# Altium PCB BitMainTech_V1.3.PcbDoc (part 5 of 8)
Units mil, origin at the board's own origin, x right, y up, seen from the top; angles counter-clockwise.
Board outline 9842.52 x 6082.68 mil, 4 copper layers (Top Layer, Mid-Layer 1, Mid-Layer 2, Bottom Layer); 987 components, 282 nets, 3694 pads, 3174 vias.
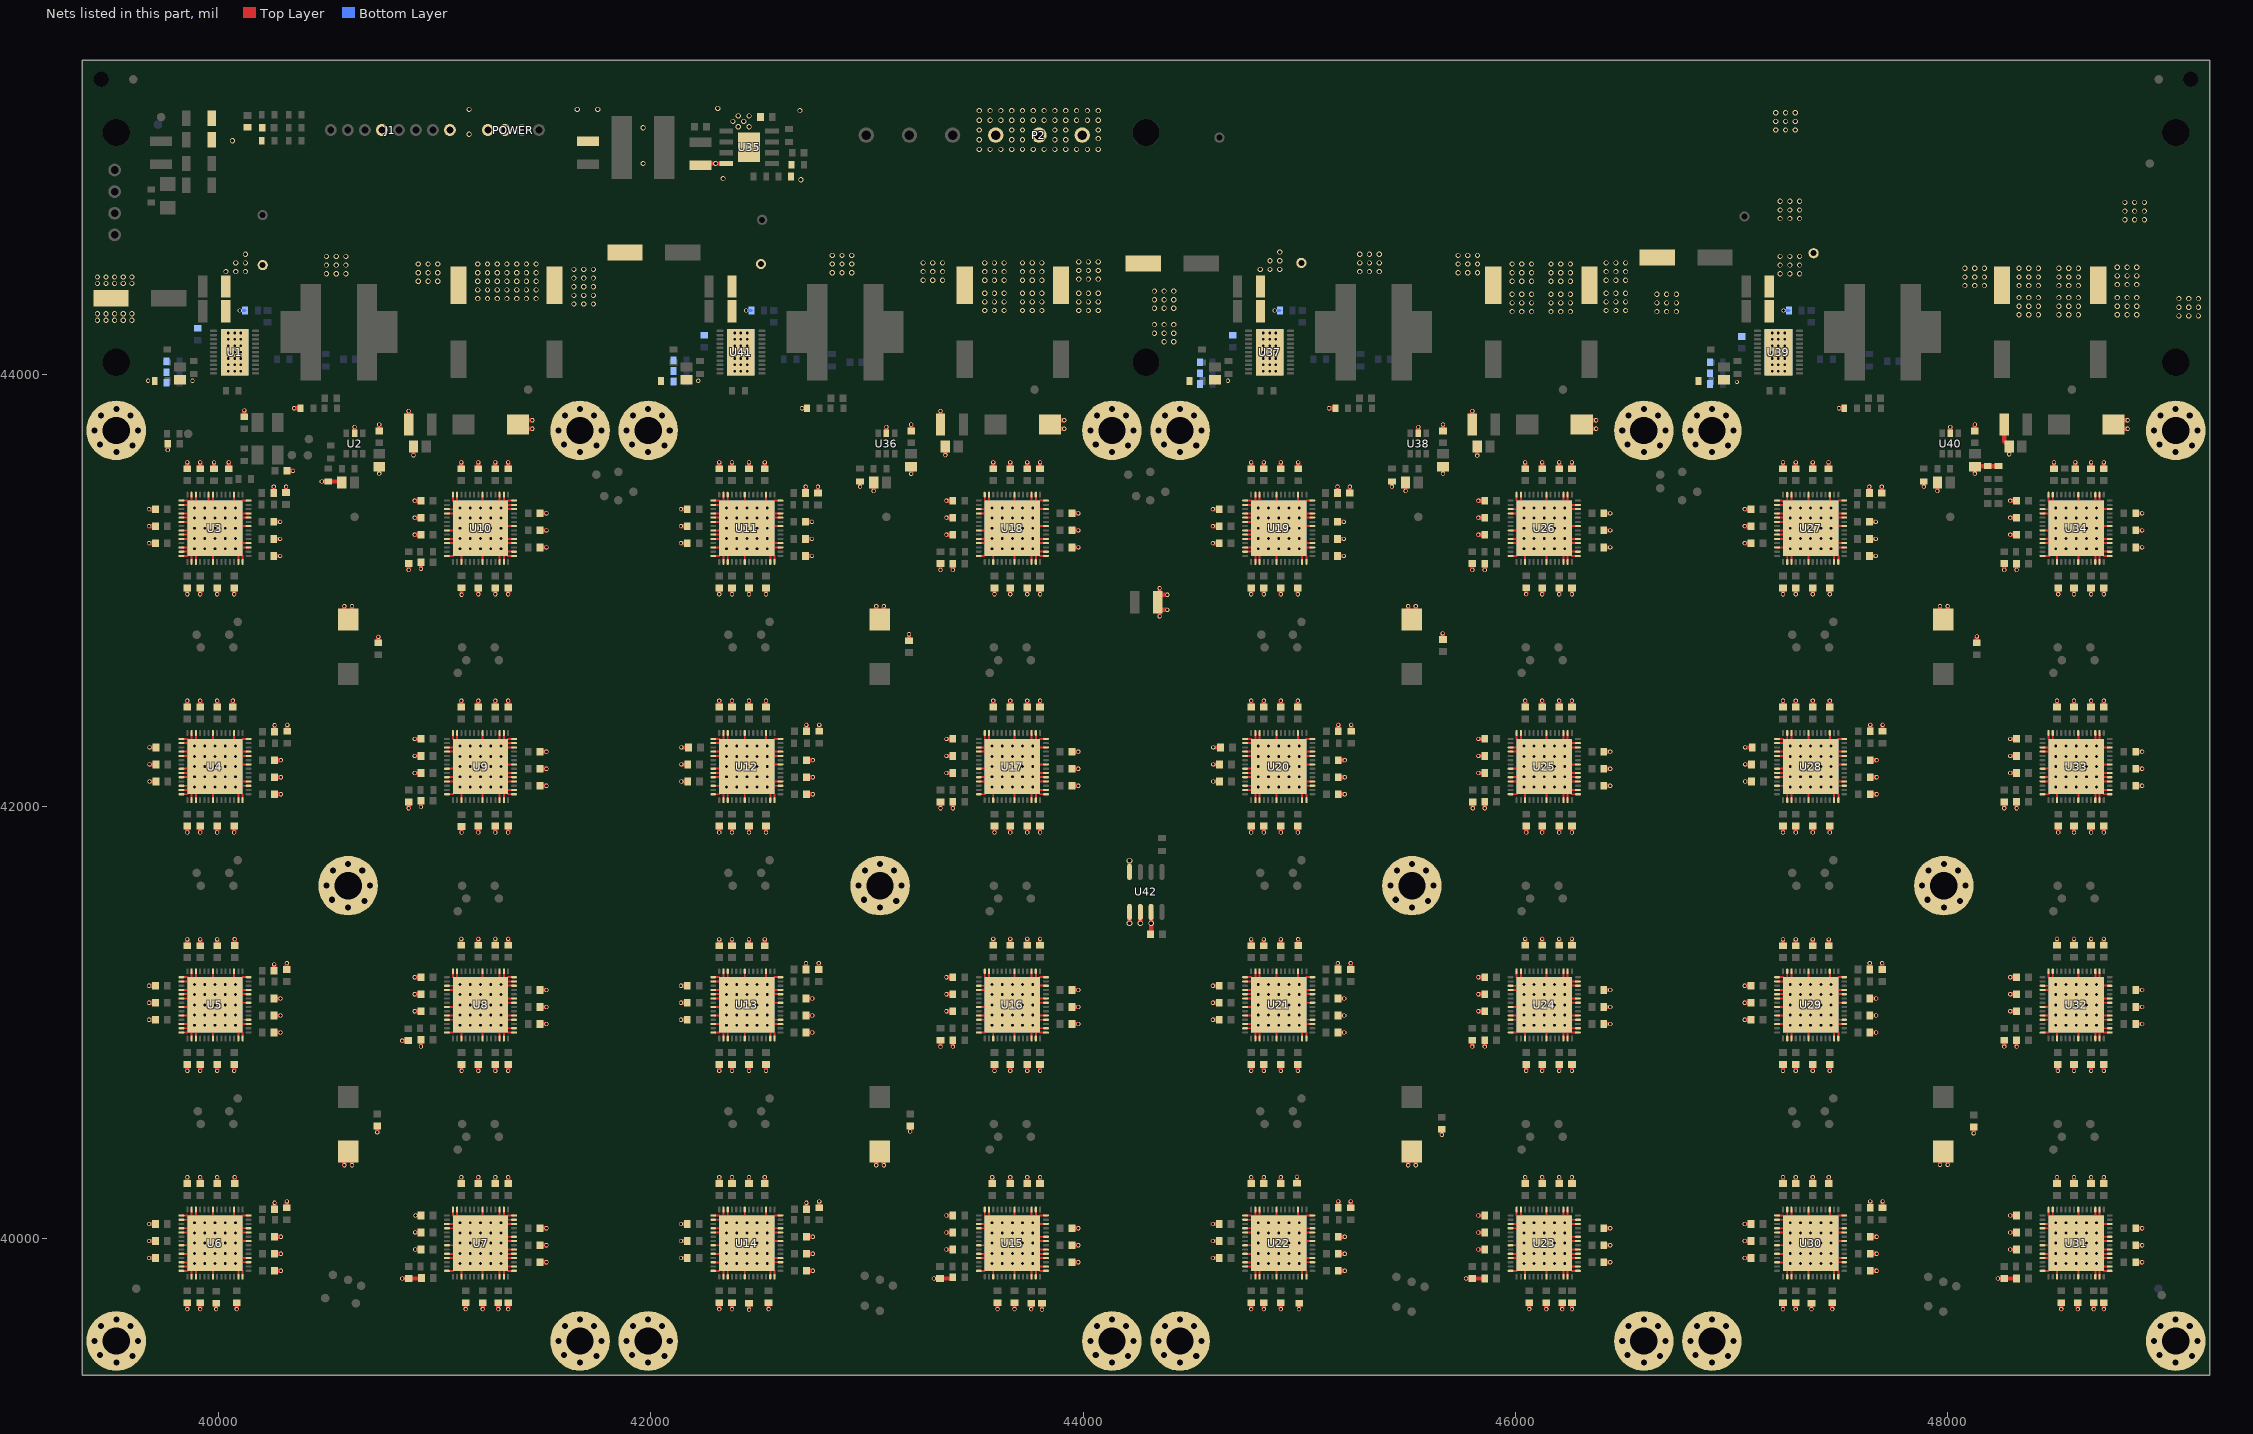
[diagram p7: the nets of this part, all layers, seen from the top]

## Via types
v1: diameter 19, hole 12, Top Layer to Bottom Layer, 1347 vias
v2: diameter 25.98, hole 12.99, Top Layer to Bottom Layer, 800 vias
v3: diameter 24, hole 16, Top Layer to Bottom Layer, 778 vias
v4: diameter 50, hole 28, Top Layer to Bottom Layer, 160 vias
v5: diameter 19.68, hole 11.81, Top Layer to Bottom Layer, 84 vias
v6: diameter 26, hole 18, Top Layer to Bottom Layer, 5 vias

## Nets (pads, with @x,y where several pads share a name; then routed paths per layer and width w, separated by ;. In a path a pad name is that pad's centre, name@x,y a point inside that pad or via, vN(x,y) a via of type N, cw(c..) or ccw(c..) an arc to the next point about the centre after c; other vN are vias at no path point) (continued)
GND: (continued)
  Top Layer w9: U6.28@39828.74,39852.36 39856.3,39852.36 U6.57@39862.2,39858.27 ; U6.27@39828.74,39872.05 U6.57@39872.05,39872.05 ; U6.26@39828.74,39891.73 U6.57@39872.05,39891.73 ; U6.24@39828.74,39931.1 U6.57@39872.05,39931.1 ; U6.22@39828.74,39970.47 U6.57@39872.05,39970.47 ; U6.19@39828.74,40029.53 U6.57@39872.05,40029.53 ; U6.18@39828.74,40049.21 U6.57@39872.05,40049.21 ; U6.16@39828.74,40088.58 U6.57@39872.05,40088.58 ; U6.15@39828.74,40108.27 39856.3,40108.27 U6.57@39862.2,40102.36 ; U5.28@39828.74,40954.72 39856.3,40954.72 U5.57@39862.2,40960.63 ; U5.27@39828.74,40974.41 U5.57@39872.05,40974.41 ; U5.26@39828.74,40994.09 U5.57@39872.05,40994.09 ; U5.24@39828.74,41033.46 U5.57@39872.05,41033.46 ; U5.22@39828.74,41072.83 U5.57@39872.05,41072.83 ; U5.20@39828.74,41112.2 U5.57@39872.05,41112.2 ; U5.19@39828.74,41131.89 U5.57@39872.05,41131.89 ; U5.18@39828.74,41151.57 U5.57@39872.05,41151.57 ; U5.16@39828.74,41190.94 U5.57@39872.05,41190.94 ; U5.15@39828.74,41210.63 39856.3,41210.63 U5.57@39862.2,41204.72 ; U4.28@39828.74,42057.09 39856.3,42057.09 U4.57@39862.2,42062.99 ; U4.27@39828.74,42076.77 U4.57@39872.05,42076.77 ; U4.26@39828.74,42096.46 U4.57@39872.05,42096.46 ; U4.24@39828.74,42135.83 U4.57@39872.05,42135.83 ; U4.23@39828.74,42155.51 U4.57@39872.05,42155.51 ; U4.22@39828.74,42175.2 U4.57@39872.05,42175.2 ; U4.19@39828.74,42234.25 U4.57@39872.05,42234.25 ; U4.18@39828.74,42253.94 U4.57@39872.05,42253.94 ; U4.16@39828.74,42293.31 U4.57@39872.05,42293.31 ; U4.15@39828.74,42312.99 39856.3,42312.99 U4.57@39862.2,42307.09 ; U3.28@39828.74,43159.45 39856.3,43159.45 U3.57@39875.98,43179.13 ; U3.27@39828.74,43179.13 U3.57@39875.98,43179.13 ; U3.26@39828.74,43198.82 U3.57@39895.67,43198.82 ; U3.24@39828.74,43238.19 U3.57@39935.04,43238.19 ; U3.23@39828.74,43257.87 U3.57@39935.04,43257.87 ; U3.22@39828.74,43277.56 U3.57@39974.41,43277.56 ; U3.20@39828.74,43316.93 U3.57@39935.04,43316.93 ; U3.19@39828.74,43336.61 U3.57@39935.04,43336.61 ; U3.18@39828.74,43356.3 U3.57@39915.35,43356.3 ; U3.16@39828.74,43395.67 U3.57@39875.98,43395.67 ; U3.15@39828.74,43415.35 39856.3,43415.35 U3.57@39875.98,43395.67 ; U6.30@39875.98,39824.8 U6.57@39875.98,39868.11 ; U6.57@39875.98,40092.52 U6.13@39875.98,40135.83 ; U5.30@39875.98,40927.17 U5.57@39875.98,40970.47 ; U5.57@39875.98,41194.88 U5.13@39875.98,41238.19 ; U4.30@39875.98,42029.53 U4.57@39875.98,42072.83 ; U4.57@39875.98,42297.24 U4.13@39875.98,42340.55 ; U3.30@39875.98,43131.89 U3.57@39875.98,43179.13 ; U3.13@39875.98,43442.91 U3.57@39875.98,43395.67 ; U6.31@39895.67,39824.8 U6.57@39895.67,39868.11 ; U6.57@39895.67,40092.52 U6.12@39895.67,40135.83 ; U5.31@39895.67,40927.17 U5.57@39895.67,40970.47 ; U5.57@39895.67,41194.88 U5.12@39895.67,41238.19 ; U4.31@39895.67,42029.53 U4.57@39895.67,42072.83 ; U4.57@39895.67,42297.24 U4.12@39895.67,42340.55 ; U3.31@39895.67,43131.89 U3.57@39895.67,43198.82 ; U3.12@39895.67,43442.91 U3.57@39895.67,43375.98 ; U3.9@39954.72,43442.91 U3.57@39954.72,43316.93 ; U6.35@39974.41,39824.8 U6.57@39974.41,39868.11 ; U6.57@39974.41,40092.52 U6.8@39974.41,40135.83 ; U5.35@39974.41,40927.17 U5.57@39974.41,40970.47 ; U5.57@39974.41,41194.88 U5.8@39974.41,41238.19 ; U4.35@39974.41,42029.53 U4.57@39974.41,42072.83 ; U4.57@39974.41,42297.24 U4.8@39974.41,42340.55 ; U3.35@39974.41,43131.89 U3.57@39974.41,43277.56 ; U3.8@39974.41,43442.91 U3.57@39974.41,43297.24 ; U6.57@40072.83,40092.52 U6.3@40072.83,40135.83 ; U5.57@40072.83,41194.88 U5.3@40072.83,41238.19 ; U4.57@40072.83,42297.24 U4.3@40072.83,42340.55 ; U3.3@40072.83,43442.91 U3.57@40072.83,43375.98 ; U6.41@40092.52,39824.8 U6.57@40092.52,39868.11 ; U5.41@40092.52,40927.17 U5.57@40092.52,40970.47 ; U4.41@40092.52,42029.53 U4.57@40092.52,42072.83 ; U3.41@40092.52,43131.89 U3.57@40092.52,43179.13 ; U6.57@40096.46,39911.42 U6.46@40139.76,39911.42 ; U6.57@40096.46,39990.16 U6.50@40139.76,39990.16 ; U6.57@40096.46,40029.53 U6.52@40139.76,40029.53 ; U6.57@40096.46,40049.21 U6.53@40139.76,40049.21 ; U5.57@40096.46,41013.78 U5.46@40139.76,41013.78 ; U5.57@40096.46,41092.52 U5.50@40139.76,41092.52 ; U5.57@40096.46,41131.89 U5.52@40139.76,41131.89 ; U5.57@40096.46,41151.57 U5.53@40139.76,41151.57 ; U4.57@40096.46,42116.14 U4.46@40139.76,42116.14 ; U4.57@40096.46,42194.88 U4.50@40139.76,42194.88 ; U4.57@40096.46,42234.25 U4.52@40139.76,42234.25 ; U4.57@40096.46,42253.94 U4.53@40139.76,42253.94 ; U6.57@40098.43,40094.49 40112.2,40108.27 U6.56@40139.76,40108.27 ; U5.57@40098.43,41196.85 40112.2,41210.63 U5.56@40139.76,41210.63 ; U4.57@40098.43,42299.21 40112.2,42312.99 U4.56@40139.76,42312.99 ; U6.57@40102.36,39862.2 40112.2,39852.36 U6.42@40112.2,39824.8 ; U5.57@40102.36,40964.57 40112.2,40954.72 U5.42@40112.2,40927.17 ; U4.57@40102.36,42066.93 40112.2,42057.09 U4.42@40112.2,42029.53 ; U3.42@40112.2,43131.89 40112.2,43159.45 U3.57@40092.52,43179.13 ; U3.46@40139.76,43218.5 U3.57@40053.15,43218.5 ; U3.50@40139.76,43297.24 U3.57@39994.09,43297.24 ; U3.52@40139.76,43336.61 U3.57@40033.46,43336.61 ; U3.53@40139.76,43356.3 U3.57@40053.15,43356.3 ; U3.56@40139.76,43415.35 40112.2,43415.35 v2(40078.74,43381.89) U3.57@40072.83,43375.98 ; U7.56@41057.09,39852.36 41084.65,39852.36 U7.57@41098.43,39866.14 ; U7.53@41057.09,39911.42 U7.57@41100.39,39911.42 ; U7.52@41057.09,39931.1 U7.57@41100.39,39931.1 ; U7.50@41057.09,39970.47 U7.57@41100.39,39970.47 ; U7.46@41057.09,40049.21 U7.57@41100.39,40049.21 ; U8.56@41057.09,40954.72 41084.65,40954.72 U8.57@41098.43,40968.5 ; U8.53@41057.09,41013.78 U8.57@41100.39,41013.78 ; U8.52@41057.09,41033.46 U8.57@41100.39,41033.46 ; U8.50@41057.09,41072.83 U8.57@41100.39,41072.83 ; U8.46@41057.09,41151.57 U8.57@41100.39,41151.57 ; U9.56@41057.09,42057.09 41084.65,42057.09 U9.57@41098.43,42070.87 ; U9.53@41057.09,42116.14 U9.57@41100.39,42116.14 ; U9.52@41057.09,42135.83 U9.57@41100.39,42135.83 ; U9.50@41057.09,42175.2 U9.57@41100.39,42175.2 ; U9.46@41057.09,42253.94 U9.57@41100.39,42253.94 ; U10.56@41057.09,43159.45 41084.65,43159.45 v2(41118.11,43192.91) U10.57@41124.02,43198.82 ; U10.53@41057.09,43218.5 U10.57@41143.7,43218.5 ; U10.52@41057.09,43238.19 U10.57@41163.39,43238.19 ; U10.50@41057.09,43277.56 41202.76,43277.56 v2(41165.35,43240.16) U10.57@41163.39,43238.19 ; U10.46@41057.09,43356.3 U10.57@41143.7,43356.3 ; U7.42@41084.65,40135.83 41084.65,40108.27 U7.57@41090.55,40102.36 ; U8.42@41084.65,41238.19 41084.65,41210.63 U8.57@41090.55,41204.72 ; U9.42@41084.65,42340.55 41084.65,42312.99 U9.57@41090.55,42307.09 ; U10.42@41084.65,43442.91 41084.65,43415.35 41104.33,43395.67 U10.41@41104.33,43442.91 ; U7.57@41104.33,40092.52 U7.41@41104.33,40135.83 ; U8.57@41104.33,41194.88 U8.41@41104.33,41238.19 ; U9.57@41104.33,42297.24 U9.41@41104.33,42340.55 ; U7.3@41124.02,39824.8 U7.57@41124.02,39868.11 ; U8.3@41124.02,40927.17 U8.57@41124.02,40970.47 ; U9.3@41124.02,42029.53 U9.57@41124.02,42072.83 ; U10.3@41124.02,43131.89 U10.57@41124.02,43198.82 ; U7.8@41222.44,39824.8 U7.57@41222.44,39868.11 ; U7.57@41222.44,40092.52 U7.35@41222.44,40135.83 ; U8.8@41222.44,40927.17 U8.57@41222.44,40970.47 ; U8.57@41222.44,41194.88 U8.35@41222.44,41238.19 ; U9.8@41222.44,42029.53 U9.57@41222.44,42072.83 ; U9.57@41222.44,42297.24 U9.35@41222.44,42340.55 ; U10.8@41222.44,43131.89 41222.44,43277.56 v2(41259.84,43240.16) U10.57@41261.81,43238.19 ; U10.35@41222.44,43442.91 41222.44,43297.24 U10.22@41368.11,43297.24 ; U7.12@41301.18,39824.8 U7.57@41301.18,39868.11 ; U7.57@41301.18,40068.9 U7.26@41368.11,40068.9 ; U7.57@41301.18,40092.52 U7.31@41301.18,40135.83 ; U8.12@41301.18,40927.17 U8.57@41301.18,40970.47 ; U8.57@41301.18,41171.26 U8.26@41368.11,41171.26 ; U8.57@41301.18,41194.88 U8.31@41301.18,41238.19 ; U9.12@41301.18,42029.53 U9.57@41301.18,42072.83 ; U9.57@41301.18,42297.24 U9.31@41301.18,42340.55 ; U10.12@41301.18,43131.89 U10.57@41301.18,43198.82 ; U10.31@41301.18,43442.91 41301.18,43375.98 U10.26@41368.11,43375.98 ; U7.13@41320.87,39824.8 U7.57@41320.87,39868.11 ; U7.57@41320.87,40092.52 U7.30@41320.87,40135.83 ; U8.13@41320.87,40927.17 U8.57@41320.87,40970.47 ; U8.57@41320.87,41194.88 U8.30@41320.87,41238.19 ; U9.13@41320.87,42029.53 U9.57@41320.87,42072.83 ; U9.57@41320.87,42297.24 U9.30@41320.87,42340.55 ; U10.13@41320.87,43131.89 U10.57@41320.87,43179.13 ; U10.30@41320.87,43442.91 U10.57@41320.87,43395.67 ; U7.57@41324.8,39872.05 U7.16@41368.11,39872.05 ; U7.57@41324.8,39911.42 U7.18@41368.11,39911.42 ; U7.57@41324.8,39931.1 U7.19@41368.11,39931.1 ; U7.57@41324.8,39950.79 U7.20@41368.11,39950.79 ; U7.57@41324.8,39990.16 U7.22@41368.11,39990.16 ; U7.57@41324.8,40009.84 U7.23@41368.11,40009.84 ; U8.57@41324.8,40974.41 U8.16@41368.11,40974.41 ; U8.57@41324.8,41013.78 U8.18@41368.11,41013.78 ; U8.57@41324.8,41033.46 U8.19@41368.11,41033.46 ; U8.57@41324.8,41092.52 U8.22@41368.11,41092.52 ; U8.57@41324.8,41112.2 U8.23@41368.11,41112.2 ; U9.57@41324.8,42076.77 U9.16@41368.11,42076.77 ; U9.57@41324.8,42116.14 U9.18@41368.11,42116.14 ; U9.57@41324.8,42135.83 U9.19@41368.11,42135.83 ; U9.57@41324.8,42155.51 U9.20@41368.11,42155.51 ; U9.57@41324.8,42194.88 U9.22@41368.11,42194.88 ; U9.57@41324.8,42273.62 U9.26@41368.11,42273.62 ; U7.57@41330.71,39862.2 41340.55,39852.36 U7.15@41368.11,39852.36 ; U8.57@41330.71,40964.57 41340.55,40954.72 U8.15@41368.11,40954.72 ; U9.57@41330.71,42066.93 41340.55,42057.09 U9.15@41368.11,42057.09 ; U7.27@41368.11,40088.58 41320.87,40088.58 41340.55,40108.27 U7.28@41368.11,40108.27 ; U8.27@41368.11,41190.94 41320.87,41190.94 41340.55,41210.63 U8.28@41368.11,41210.63 ; U9.27@41368.11,42293.31 41320.87,42293.31 41340.55,42312.99 U9.28@41368.11,42312.99 ; U10.15@41368.11,43159.45 41340.55,43159.45 U10.57@41320.87,43179.13 ; U10.16@41368.11,43179.13 U10.57@41320.87,43179.13 ; U10.18@41368.11,43218.5 U10.57@41281.5,43218.5 ; U10.19@41368.11,43238.19 U10.57@41261.81,43238.19 ; U10.27@41368.11,43395.67 U10.57@41320.87,43395.67 ; U10.28@41368.11,43415.35 41340.55,43415.35 U10.57@41320.87,43395.67 ; U14.28@42289.37,39852.36 42316.93,39852.36 U14.57@42322.83,39858.27 ; U14.26@42289.37,39891.73 U14.57@42332.68,39891.73 ; U14.24@42289.37,39931.1 U14.57@42332.68,39931.1 ; U14.22@42289.37,39970.47 U14.57@42332.68,39970.47 ; U14.19@42289.37,40029.53 U14.57@42332.68,40029.53 ; U14.18@42289.37,40049.21 U14.57@42332.68,40049.21 ; U14.16@42289.37,40088.58 U14.57@42332.68,40088.58 ; U14.15@42289.37,40108.27 42316.93,40108.27 U14.57@42322.83,40102.36 ; U13.28@42289.37,40954.72 42316.93,40954.72 U13.57@42326.77,40964.57 ; U13.26@42289.37,40994.09 U13.57@42332.68,40994.09 ; U13.24@42289.37,41033.46 U13.57@42332.68,41033.46 ; U13.22@42289.37,41072.83 U13.57@42332.68,41072.83 ; U13.20@42289.37,41112.2 U13.57@42332.68,41112.2 ; U13.19@42289.37,41131.89 U13.57@42332.68,41131.89 ; U13.18@42289.37,41151.57 U13.57@42332.68,41151.57 ; U13.16@42289.37,41190.94 U13.57@42332.68,41190.94 ; U13.15@42289.37,41210.63 42316.93,41210.63 U13.57@42322.83,41204.72 ; U12.28@42289.37,42057.09 42316.93,42057.09 U12.57@42326.77,42066.93 ; U12.26@42289.37,42096.46 U12.57@42332.68,42096.46 ; U12.24@42289.37,42135.83 U12.57@42332.68,42135.83 ; U12.23@42289.37,42155.51 U12.57@42332.68,42155.51 ; U12.22@42289.37,42175.2 U12.57@42332.68,42175.2 ; U12.19@42289.37,42234.25 U12.57@42332.68,42234.25 ; U12.18@42289.37,42253.94 U12.57@42332.68,42253.94 ; U12.16@42289.37,42293.31 U12.57@42332.68,42293.31 ; U12.15@42289.37,42312.99 42316.93,42312.99 U12.57@42322.83,42307.09 ; U11.28@42289.37,43159.45 42316.93,43159.45 U11.57@42326.77,43169.29 ; U11.26@42289.37,43198.82 U11.57@42332.68,43198.82 ; U11.24@42289.37,43238.19 U11.57@42332.68,43238.19 ; U11.23@42289.37,43257.87 U11.57@42332.68,43257.87 ; U11.22@42289.37,43277.56 U11.57@42332.68,43277.56 ; U11.20@42289.37,43316.93 U11.57@42332.68,43316.93 ; U11.19@42289.37,43336.61 U11.57@42332.68,43336.61 ; U11.18@42289.37,43356.3 U11.57@42332.68,43356.3 ; U11.16@42289.37,43395.67 U11.57@42332.68,43395.67 ; U11.15@42289.37,43415.35 42316.93,43415.35 U11.57@42322.83,43409.45 ; U14.30@42336.61,39824.8 U14.57@42336.61,39868.11 ; U14.57@42336.61,40092.52 U14.13@42336.61,40135.83 ; U13.30@42336.61,40927.17 U13.57@42336.61,40970.47 ; U13.57@42336.61,41194.88 U13.13@42336.61,41238.19 ; U12.30@42336.61,42029.53 U12.57@42336.61,42072.83 ; U12.57@42336.61,42297.24 U12.13@42336.61,42340.55 ; U11.30@42336.61,43131.89 U11.57@42336.61,43175.2 ; U11.57@42336.61,43399.61 U11.13@42336.61,43442.91 ; U14.31@42356.3,39824.8 U14.57@42356.3,39868.11 ; U14.57@42356.3,40092.52 U14.12@42356.3,40135.83 ; U13.31@42356.3,40927.17 U13.57@42356.3,40970.47 ; U13.57@42356.3,41194.88 U13.12@42356.3,41238.19 ; U12.31@42356.3,42029.53 U12.57@42356.3,42072.83 ; U12.57@42356.3,42297.24 U12.12@42356.3,42340.55 ; U11.31@42356.3,43131.89 U11.57@42356.3,43175.2 ; U11.57@42356.3,43399.61 U11.12@42356.3,43442.91 ; U14.35@42435.04,39824.8 U14.57@42435.04,39868.11 ; U14.57@42435.04,40092.52 U14.8@42435.04,40135.83 ; U13.35@42435.04,40927.17 U13.57@42435.04,40970.47 ; U13.57@42435.04,41194.88 U13.8@42435.04,41238.19 ; U12.35@42435.04,42029.53 U12.57@42435.04,42072.83 ; U12.57@42435.04,42297.24 U12.8@42435.04,42340.55 ; U11.35@42435.04,43131.89 U11.57@42435.04,43175.2 ; U11.57@42435.04,43399.61 U11.8@42435.04,43442.91 ; U14.57@42533.46,40092.52 U14.3@42533.46,40135.83 ; U13.57@42533.46,41194.88 U13.3@42533.46,41238.19 ; U12.57@42533.46,42297.24 U12.3@42533.46,42340.55 ; U11.57@42533.46,43399.61 U11.3@42533.46,43442.91 ; U14.41@42553.15,39824.8 U14.57@42553.15,39868.11 ; U13.41@42553.15,40927.17 U13.57@42553.15,40970.47 ; U12.41@42553.15,42029.53 U12.57@42553.15,42072.83 ; U11.41@42553.15,43131.89 U11.57@42553.15,43175.2 ; U14.57@42557.09,39911.42 U14.46@42600.39,39911.42 ; U14.57@42557.09,39990.16 U14.50@42600.39,39990.16 ; U14.57@42557.09,40029.53 U14.52@42600.39,40029.53 ; U14.57@42557.09,40049.21 U14.53@42600.39,40049.21 ; U13.57@42557.09,41013.78 U13.46@42600.39,41013.78 ; U13.57@42557.09,41092.52 U13.50@42600.39,41092.52 ; U13.57@42557.09,41131.89 U13.52@42600.39,41131.89 ; U13.57@42557.09,41151.57 U13.53@42600.39,41151.57 ; U12.57@42557.09,42116.14 U12.46@42600.39,42116.14 ; U12.57@42557.09,42194.88 U12.50@42600.39,42194.88 ; U12.57@42557.09,42234.25 U12.52@42600.39,42234.25 ; U12.57@42557.09,42253.94 U12.53@42600.39,42253.94 ; U11.57@42557.09,43218.5 U11.46@42600.39,43218.5 ; U11.57@42557.09,43297.24 U11.50@42600.39,43297.24 ; U11.57@42557.09,43336.61 U11.52@42600.39,43336.61 ; U11.57@42557.09,43356.3 U11.53@42600.39,43356.3 ; U14.57@42559.06,40094.49 42572.83,40108.27 U14.56@42600.39,40108.27 ; U13.57@42559.06,41196.85 42572.83,41210.63 U13.56@42600.39,41210.63 ; U12.57@42559.06,42299.21 42572.83,42312.99 U12.56@42600.39,42312.99 ; U11.57@42559.06,43401.57 42572.83,43415.35 U11.56@42600.39,43415.35 ; U14.57@42562.99,39862.2 42572.83,39852.36 U14.42@42572.83,39824.8 ; U13.57@42562.99,40964.57 42572.83,40954.72 U13.42@42572.83,40927.17 ; U12.57@42562.99,42066.93 42572.83,42057.09 U12.42@42572.83,42029.53 ; U11.57@42562.99,43169.29 42572.83,43159.45 U11.42@42572.83,43131.89 ; U15.56@43517.72,39852.36 43545.28,39852.36 U15.57@43559.06,39866.14 ; U15.53@43517.72,39911.42 U15.57@43561.02,39911.42 ; U15.52@43517.72,39931.1 U15.57@43561.02,39931.1 ; U15.50@43517.72,39970.47 U15.57@43561.02,39970.47 ; U15.46@43517.72,40049.21 U15.57@43561.02,40049.21 ; U16.56@43517.72,40954.72 43545.28,40954.72 U16.57@43559.05,40968.5 ; U16.53@43517.72,41013.78 U16.57@43561.02,41013.78 ; U16.52@43517.72,41033.46 U16.57@43561.02,41033.46 ; U16.50@43517.72,41072.83 U16.57@43561.02,41072.83 ; U16.46@43517.72,41151.57 U16.57@43561.02,41151.57 ; U17.56@43517.72,42057.09 43545.28,42057.09 U17.57@43559.05,42070.87 ; U17.53@43517.72,42116.14 U17.57@43561.02,42116.14 ; U17.52@43517.72,42135.83 U17.57@43561.02,42135.83 ; U17.50@43517.72,42175.2 U17.57@43561.02,42175.2 ; U17.46@43517.72,42253.94 U17.57@43561.02,42253.94 ; U18.56@43517.72,43159.45 43541.34,43159.45 U18.57@43559.06,43177.17 ; U18.53@43517.72,43218.5 U18.57@43561.02,43218.5 ; U18.52@43517.72,43238.19 U18.57@43561.02,43238.19 ; U18.50@43517.72,43277.56 U18.57@43561.02,43277.56 ; U18.46@43517.72,43356.3 U18.57@43561.02,43356.3 ; U15.42@43545.28,40135.83 43545.28,40108.27 U15.57@43551.18,40102.36 ; U16.42@43545.28,41238.19 43545.28,41210.63 U16.57@43551.18,41204.72 ; U18.42@43545.28,43442.91 43545.28,43415.35 U18.57@43555.12,43405.51 ; U17.57@43551.18,42307.09 U17.57@43545.28,42312.99 ; U17.57@43555.12,42303.15 43545.28,42312.99 ; U15.57@43564.96,40092.52 U15.41@43564.96,40135.83 ; U16.57@43564.96,41194.88 U16.41@43564.96,41238.19 ; U17.57@43564.96,42297.24 U17.41@43564.96,42340.55 ; U18.57@43564.96,43399.61 U18.41@43564.96,43442.91 ; U15.3@43584.65,39824.8 U15.57@43584.65,39868.11 ; U16.3@43584.65,40927.17 U16.57@43584.65,40970.47 ; U17.3@43584.65,42029.53 U17.57@43584.65,42072.83 ; U18.3@43584.65,43131.89 U18.57@43584.65,43175.2 ; U15.8@43683.07,39824.8 U15.57@43683.07,39868.11 ; U15.57@43683.07,40092.52 U15.35@43683.07,40135.83 ; U16.8@43683.07,40927.17 U16.57@43683.07,40970.47 ; U16.57@43683.07,41194.88 U16.35@43683.07,41238.19 ; U17.8@43683.07,42029.53 U17.57@43683.07,42072.83 ; U17.57@43683.07,42297.24 U17.35@43683.07,42340.55 ; U18.8@43683.07,43131.89 U18.57@43683.07,43175.2 ; U18.57@43683.07,43399.61 U18.35@43683.07,43442.91 ; U15.12@43761.81,39824.8 U15.57@43761.81,39868.11 ; U15.57@43761.81,40068.9 U15.26@43828.74,40068.9 ; U15.57@43761.81,40092.52 U15.31@43761.81,40135.83 ; U16.12@43761.81,40927.17 U16.57@43761.81,40970.47 ; U16.57@43761.81,41171.26 U16.26@43828.74,41171.26 ; U16.57@43761.81,41194.88 U16.31@43761.81,41238.19 ; U17.12@43761.81,42029.53 U17.57@43761.81,42072.83 ; U17.57@43761.81,42273.62 U17.26@43828.74,42273.62 ; U17.57@43761.81,42297.24 U17.31@43761.81,42340.55 ; U18.12@43761.81,43131.89 U18.57@43761.81,43175.2 ; U18.57@43761.81,43399.61 U18.31@43761.81,43442.91 ; U15.13@43781.5,39824.8 U15.57@43781.5,39868.11 ; U15.57@43781.5,40088.58 43801.18,40108.27 U15.28@43828.74,40108.27 ; U15.57@43781.5,40092.52 U15.30@43781.5,40135.83 ; U16.13@43781.5,40927.17 U16.57@43781.5,40970.47 ; U16.57@43781.5,41190.94 43801.18,41210.63 U16.28@43828.74,41210.63 ; U16.57@43781.5,41194.88 U16.30@43781.5,41238.19 ; U17.13@43781.5,42029.53 U17.57@43781.5,42072.83 ; U17.57@43781.5,42293.31 43801.18,42312.99 ; U17.57@43781.5,42297.24 U17.30@43781.5,42340.55 ; U18.13@43781.5,43131.89 U18.57@43781.5,43175.2 ; U18.57@43781.5,43399.61 U18.30@43781.5,43442.91 ; U15.57@43785.43,39872.05 U15.16@43828.74,39872.05 ; U15.57@43785.43,39911.42 U15.18@43828.74,39911.42 ; U15.57@43785.43,39931.1 U15.19@43828.74,39931.1 ; U15.57@43785.43,39950.79 U15.20@43828.74,39950.79 ; U15.57@43785.43,39990.16 U15.22@43828.74,39990.16 ; U15.57@43785.43,40009.84 U15.23@43828.74,40009.84 ; U16.57@43785.43,40974.41 U16.16@43828.74,40974.41 ; U16.57@43785.43,41013.78 U16.18@43828.74,41013.78 ; U16.57@43785.43,41033.46 U16.19@43828.74,41033.46 ; U16.57@43785.43,41092.52 U16.22@43828.74,41092.52 ; U16.57@43785.43,41112.2 U16.23@43828.74,41112.2 ; U17.57@43785.43,42076.77 U17.16@43828.74,42076.77 ; U17.57@43785.43,42116.14 U17.18@43828.74,42116.14 ; U17.57@43785.43,42135.83 U17.19@43828.74,42135.83 ; U17.57@43785.43,42155.51 U17.20@43828.74,42155.51 ; U17.57@43785.43,42194.88 U17.22@43828.74,42194.88 ; U18.57@43785.43,43179.13 U18.16@43828.74,43179.13 ; U18.57@43785.43,43218.5 U18.18@43828.74,43218.5 ; U18.57@43785.43,43238.19 U18.19@43828.74,43238.19 ; U18.57@43785.43,43297.24 U18.22@43828.74,43297.24 ; U18.57@43785.43,43375.98 U18.26@43828.74,43375.98 ; U15.57@43791.34,39862.2 43801.18,39852.36 U15.15@43828.74,39852.36 ; U16.57@43791.34,40964.57 43801.18,40954.72 U16.15@43828.74,40954.72 ; U17.57@43791.34,42066.93 43801.18,42057.09 U17.15@43828.74,42057.09 ; U18.57@43791.34,43169.29 43801.18,43159.45 U18.15@43828.74,43159.45 ; U17.57@43795.28,42307.09 43801.18,42312.99 ; U18.57@43795.28,43409.45 43801.18,43415.35 U18.28@43828.74,43415.35 ; U22.27@44750,39872.05 U22.57@44793.31,39872.05 ; U22.26@44750,39891.73 U22.57@44793.31,39891.73 ; U22.24@44750,39931.1 U22.57@44793.31,39931.1 ; U22.22@44750,39970.47 U22.57@44793.31,39970.47 ; U22.19@44750,40029.53 U22.57@44793.31,40029.53 ; U22.18@44750,40049.21 U22.57@44793.31,40049.21 ; U22.16@44750,40088.58 U22.57@44793.31,40088.58 ; U22.15@44750,40108.27 44777.56,40108.27 U22.57@44787.4,40098.43 ; U21.27@44750,40974.41 U21.57@44793.31,40974.41 ; U21.26@44750,40994.09 U21.57@44793.31,40994.09 ; U21.24@44750,41033.46 U21.57@44793.31,41033.46 ; U21.22@44750,41072.83 U21.57@44793.31,41072.83 ; U21.20@44750,41112.2 U21.57@44793.31,41112.2 ; U21.19@44750,41131.89 U21.57@44793.31,41131.89 ; U21.18@44750,41151.57 U21.57@44793.31,41151.57 ; U21.16@44750,41190.94 U21.57@44793.31,41190.94 ; U21.15@44750,41210.63 44777.56,41210.63 U21.57@44787.4,41200.79 ; U20.27@44750,42076.77 U20.57@44793.31,42076.77 ; U20.26@44750,42096.46 U20.57@44793.31,42096.46 ; U20.24@44750,42135.83 U20.57@44793.31,42135.83 ; U20.23@44750,42155.51 U20.57@44793.31,42155.51 ; U20.22@44750,42175.2 U20.57@44793.31,42175.2 ; U20.19@44750,42234.25 U20.57@44793.31,42234.25 ; U20.18@44750,42253.94 U20.57@44793.31,42253.94 ; U20.16@44750,42293.31 U20.57@44793.31,42293.31 ; U20.15@44750,42312.99 44777.56,42312.99 U20.57@44783.46,42307.09 ; U19.27@44750,43179.13 U19.57@44793.31,43179.13 ; U19.26@44750,43198.82 U19.57@44793.31,43198.82 ; U19.24@44750,43238.19 U19.57@44793.31,43238.19 ; U19.23@44750,43257.87 U19.57@44793.31,43257.87 ; U19.22@44750,43277.56 U19.57@44793.31,43277.56 ; U19.20@44750,43316.93 U19.57@44793.31,43316.93 ; U19.19@44750,43336.61 U19.57@44793.31,43336.61 ; U19.18@44750,43356.3 U19.57@44793.31,43356.3 ; U19.16@44750,43395.67 U19.57@44793.31,43395.67 ; U19.15@44750,43415.35 44777.56,43415.35 U19.57@44787.4,43405.51 ; U22.30@44797.24,39824.8 U22.57@44797.24,39868.11 ; U22.57@44797.24,40092.52 U22.13@44797.24,40135.83 ; U21.30@44797.24,40927.17 U21.57@44797.24,40970.47 ; U21.57@44797.24,41194.88 U21.13@44797.24,41238.19 ; U20.30@44797.24,42029.53 U20.57@44797.24,42072.83 ; U20.57@44797.24,42297.24 U20.13@44797.24,42340.55 ; U19.30@44797.24,43131.89 U19.57@44797.24,43175.2 ; U19.57@44797.24,43399.61 U19.13@44797.24,43442.91 ; U22.31@44816.93,39824.8 U22.57@44816.93,39868.11 ; U22.57@44816.93,40092.52 U22.12@44816.93,40135.83 ; U21.31@44816.93,40927.17 U21.57@44816.93,40970.47 ; U21.57@44816.93,41194.88 U21.12@44816.93,41238.19 ; U20.31@44816.93,42029.53 U20.57@44816.93,42072.83 ; U20.57@44816.93,42297.24 U20.12@44816.93,42340.55 ; U19.31@44816.93,43131.89 U19.57@44816.93,43175.2 ; U19.57@44816.93,43399.61 U19.12@44816.93,43442.91 ; U22.35@44895.67,39824.8 U22.57@44895.67,39868.11 ; U22.57@44895.67,40092.52 U22.8@44895.67,40135.83 ; U21.35@44895.67,40927.17 U21.57@44895.67,40970.47 ; U21.57@44895.67,41194.88 U21.8@44895.67,41238.19 ; U20.35@44895.67,42029.53 U20.57@44895.67,42072.83 ; U20.57@44895.67,42297.24 U20.8@44895.67,42340.55 ; U19.35@44895.67,43131.89 U19.57@44895.67,43175.2 ; U19.57@44895.67,43399.61 U19.8@44895.67,43442.91 ; U22.57@44994.09,40092.52 U22.3@44994.09,40135.83 ; U21.57@44994.09,41194.88 U21.3@44994.09,41238.19 ; U20.57@44994.09,42297.24 U20.3@44994.09,42340.55 ; U19.57@44994.09,43399.61 U19.3@44994.09,43442.91 ; U22.41@45013.78,39824.8 U22.57@45013.78,39868.11 ; U21.41@45013.78,40927.17 U21.57@45013.78,40970.47 ; U20.41@45013.78,42029.53 U20.57@45013.78,42072.83 ; U19.41@45013.78,43131.89 U19.57@45013.78,43175.2 ; U22.57@45017.72,39911.42 U22.46@45061.02,39911.42 ; U22.57@45017.72,39990.16 U22.50@45061.02,39990.16 ; U22.57@45017.72,40029.53 U22.52@45061.02,40029.53 ; U22.57@45017.72,40049.21 U22.53@45061.02,40049.21 ; U21.57@45017.72,41013.78 U21.46@45061.02,41013.78 ; U21.57@45017.72,41092.52 U21.50@45061.02,41092.52 ; U21.57@45017.72,41131.89 U21.52@45061.02,41131.89 ; U21.57@45017.72,41151.57 U21.53@45061.02,41151.57 ; U20.57@45017.72,42116.14 U20.46@45061.02,42116.14 ; U20.57@45017.72,42194.88 U20.50@45061.02,42194.88 ; U20.57@45017.72,42234.25 U20.52@45061.02,42234.25 ; U20.57@45017.72,42253.94 U20.53@45061.02,42253.94 ; U19.57@45017.72,43218.5 U19.46@45061.02,43218.5 ; U19.57@45017.72,43297.24 U19.50@45061.02,43297.24 ; U19.57@45017.72,43336.61 U19.52@45061.02,43336.61 ; U19.57@45017.72,43356.3 U19.53@45061.02,43356.3 ; U21.57@45019.68,41196.85 45033.46,41210.63 U21.56@45061.02,41210.63 ; U20.57@45019.68,42299.21 45033.46,42312.99 U20.56@45061.02,42312.99 ; U22.57@45023.62,40098.43 45033.46,40108.27 U22.56@45061.02,40108.27 ; U21.57@45023.62,40964.57 45033.46,40954.72 U21.42@45033.46,40927.17 ; U20.57@45023.62,42066.93 45033.46,42057.09 U20.42@45033.46,42029.53 ; U19.57@45023.62,43405.51 45033.46,43415.35 U19.56@45061.02,43415.35 ; U22.57@45027.56,39858.27 45033.46,39852.36 U22.42@45033.46,39824.8 ; U19.57@45027.56,43165.35 45033.46,43159.45 U19.42@45033.46,43131.89 ; U23.56@45978.35,39852.36 46005.91,39852.36 U23.57@46015.75,39862.2 ; U23.53@45978.35,39911.42 U23.57@46021.65,39911.42 ; U23.52@45978.35,39931.1 U23.57@46021.65,39931.1 ; U23.50@45978.35,39970.47 U23.57@46021.65,39970.47 ; U23.46@45978.35,40049.21 U23.57@46021.65,40049.21 ; U24.56@45978.35,40954.72 46005.91,40954.72 U24.57@46011.81,40960.63 ; U24.53@45978.35,41013.78 U24.57@46021.65,41013.78 ; U24.52@45978.35,41033.46 U24.57@46021.65,41033.46 ; U24.50@45978.35,41072.83 U24.57@46021.65,41072.83 ; U24.46@45978.35,41151.57 U24.57@46021.65,41151.57 ; U25.56@45978.35,42057.09 46005.91,42057.09 U25.57@46015.75,42066.93 ; U25.53@45978.35,42116.14 U25.57@46021.65,42116.14 ; U25.52@45978.35,42135.83 U25.57@46021.65,42135.83 ; U25.50@45978.35,42175.2 U25.57@46021.65,42175.2 ; U25.46@45978.35,42253.94 U25.57@46021.65,42253.94 ; U26.56@45978.35,43159.45 46005.91,43159.45 U26.57@46019.68,43173.23 ; U26.53@45978.35,43218.5 U26.57@46021.65,43218.5 ; U26.52@45978.35,43238.19 U26.57@46021.65,43238.19 ; U26.50@45978.35,43277.56 U26.57@46021.65,43277.56 ; U26.46@45978.35,43356.3 U26.57@46021.65,43356.3 ; U23.42@46005.91,40135.83 46005.91,40108.27 U23.57@46015.75,40098.43 ; U24.42@46005.91,41238.19 46005.91,41210.63 U24.57@46015.75,41200.79 ; U25.42@46005.91,42340.55 46005.91,42312.99 U25.57@46015.75,42303.15 ; U26.42@46005.91,43442.91 46005.91,43415.35 U26.57@46015.75,43405.51 ; U23.57@46025.59,40092.52 U23.41@46025.59,40135.83 ; U24.57@46025.59,41194.88 U24.41@46025.59,41238.19 ; U25.57@46025.59,42297.24 U25.41@46025.59,42340.55 ; U26.57@46025.59,43399.61 U26.41@46025.59,43442.91 ; U23.3@46045.28,39824.8 U23.57@46045.28,39868.11 ; U24.3@46045.28,40927.17 U24.57@46045.28,40970.47 ; U25.3@46045.28,42029.53 U25.57@46045.28,42072.83 ; U26.3@46045.28,43131.89 U26.57@46045.28,43175.2 ; U23.8@46143.7,39824.8 U23.57@46143.7,39868.11 ; U23.57@46143.7,40092.52 U23.35@46143.7,40135.83 ; U24.8@46143.7,40927.17 U24.57@46143.7,40970.47 ; U24.57@46143.7,41194.88 U24.35@46143.7,41238.19 ; U25.8@46143.7,42029.53 U25.57@46143.7,42072.83 ; U25.57@46143.7,42297.24 U25.35@46143.7,42340.55 ; U26.8@46143.7,43131.89 U26.57@46143.7,43175.2 ; U26.57@46143.7,43399.61 U26.35@46143.7,43442.91 ; U23.12@46222.44,39824.8 U23.57@46222.44,39868.11 ; U23.57@46222.44,40092.52 U23.31@46222.44,40135.83 ; U24.12@46222.44,40927.17 U24.57@46222.44,40970.47 ; U24.57@46222.44,41194.88 U24.31@46222.44,41238.19 ; U25.12@46222.44,42029.53 U25.57@46222.44,42072.83 ; U25.57@46222.44,42297.24 U25.31@46222.44,42340.55 ; U26.12@46222.44,43131.89 U26.57@46222.44,43175.2 ; U26.57@46222.44,43399.61 U26.31@46222.44,43442.91 ; U23.13@46242.13,39824.8 U23.57@46242.13,39868.11 ; U23.57@46242.13,40092.52 U23.30@46242.13,40135.83 ; U24.13@46242.13,40927.17 U24.57@46242.13,40970.47 ; U24.57@46242.13,41194.88 U24.30@46242.13,41238.19 ; U25.13@46242.13,42029.53 U25.57@46242.13,42072.83 ; U25.57@46242.13,42297.24 U25.30@46242.13,42340.55 ; U26.13@46242.13,43131.89 U26.57@46242.13,43175.2 ; U26.57@46242.13,43399.61 U26.30@46242.13,43442.91 ; U23.57@46246.06,39872.05 U23.16@46289.37,39872.05 ; U23.57@46246.06,39911.42 U23.18@46289.37,39911.42 ; U23.57@46246.06,39931.1 U23.19@46289.37,39931.1 ; U23.57@46246.06,39950.79 U23.20@46289.37,39950.79 ; U23.57@46246.06,39990.16 U23.22@46289.37,39990.16 ; U23.57@46246.06,40009.84 U23.23@46289.37,40009.84 ; U23.57@46246.06,40068.9 U23.26@46289.37,40068.9 ; U23.57@46246.06,40088.58 U23.27@46289.37,40088.58 ; U24.57@46246.06,40974.41 U24.16@46289.37,40974.41 ; U24.57@46246.06,41013.78 U24.18@46289.37,41013.78 ; U24.57@46246.06,41033.46 U24.19@46289.37,41033.46 ; U24.57@46246.06,41092.52 U24.22@46289.37,41092.52 ; U24.57@46246.06,41112.2 U24.23@46289.37,41112.2 ; U24.57@46246.06,41171.26 U24.26@46289.37,41171.26 ; U24.57@46246.06,41190.94 U24.27@46289.37,41190.94 ; U25.57@46246.06,42076.77 U25.16@46289.37,42076.77 ; U25.57@46246.06,42116.14 U25.18@46289.37,42116.14 ; U25.57@46246.06,42135.83 U25.19@46289.37,42135.83 ; U25.57@46246.06,42155.51 U25.20@46289.37,42155.51 ; U25.57@46246.06,42194.88 U25.22@46289.37,42194.88 ; U25.57@46246.06,42273.62 U25.26@46289.37,42273.62 ; U25.57@46246.06,42293.31 U25.27@46289.37,42293.31 ; U26.57@46246.06,43179.13 U26.16@46289.37,43179.13 ; U26.57@46246.06,43218.5 U26.18@46289.37,43218.5 ; U26.57@46246.06,43238.19 U26.19@46289.37,43238.19 ; U26.57@46246.06,43297.24 U26.22@46289.37,43297.24 ; U26.57@46246.06,43375.98 U26.26@46289.37,43375.98 ; U26.57@46246.06,43395.67 U26.27@46289.37,43395.67 ; U23.57@46251.97,39862.2 46261.81,39852.36 U23.15@46289.37,39852.36 ; U24.57@46251.97,40964.57 46261.81,40954.72 U24.15@46289.37,40954.72 ; U26.57@46251.97,43169.29 46261.81,43159.45 U26.15@46289.37,43159.45 ; U25.57@46255.91,42062.99 46261.81,42057.09 U25.15@46289.37,42057.09 ; U30.26@47210.63,39891.73 U30.57@47253.94,39891.73 ; U30.24@47210.63,39931.1 U30.57@47253.94,39931.1 ; U30.22@47210.63,39970.47 U30.57@47253.94,39970.47 ; U30.19@47210.63,40029.53 U30.57@47253.94,40029.53 ; U30.18@47210.63,40049.21 U30.57@47253.94,40049.21 ; U30.16@47210.63,40088.58 U30.57@47253.94,40088.58 ; U30.15@47210.63,40108.27 47238.19,40108.27 U30.57@47251.97,40094.49 ; U29.26@47210.63,40994.09 U29.57@47253.94,40994.09 ; U29.24@47210.63,41033.46 U29.57@47253.94,41033.46 ; U29.22@47210.63,41072.83 U29.57@47253.94,41072.83 ; U29.20@47210.63,41112.2 U29.57@47253.94,41112.2 ; U29.19@47210.63,41131.89 U29.57@47253.94,41131.89 ; U29.18@47210.63,41151.57 U29.57@47253.94,41151.57 ; U29.16@47210.63,41190.94 U29.57@47253.94,41190.94 ; U29.15@47210.63,41210.63 47238.19,41210.63 U29.57@47248.03,41200.79 ; U28.26@47210.63,42096.46 U28.57@47253.94,42096.46 ; U28.24@47210.63,42135.83 U28.57@47253.94,42135.83 ; U28.23@47210.63,42155.51 U28.57@47253.94,42155.51 ; U28.22@47210.63,42175.2 U28.57@47253.94,42175.2 ; U28.19@47210.63,42234.25 U28.57@47253.94,42234.25 ; U28.18@47210.63,42253.94 U28.57@47253.94,42253.94 ; U28.16@47210.63,42293.31 U28.57@47253.94,42293.31 ; U28.15@47210.63,42312.99 47238.19,42312.99 U28.57@47244.09,42307.09 ; U27.26@47210.63,43198.82 U27.57@47253.94,43198.82 ; U27.24@47210.63,43238.19 U27.57@47253.94,43238.19 ; U27.23@47210.63,43257.87 U27.57@47253.94,43257.87 ; U27.22@47210.63,43277.56 U27.57@47253.94,43277.56 ; U27.20@47210.63,43316.93 U27.57@47253.94,43316.93 ; U27.19@47210.63,43336.61 U27.57@47253.94,43336.61 ; U27.18@47210.63,43356.3 U27.57@47253.94,43356.3 ; U27.16@47210.63,43395.67 U27.57@47253.94,43395.67 ; U27.15@47210.63,43415.35 47234.25,43415.35 U27.57@47251.97,43397.64 ; U30.30@47257.87,39824.8 U30.57@47257.87,39868.11 ; U30.57@47257.87,40092.52 U30.13@47257.87,40135.83 ; U29.30@47257.87,40927.17 U29.57@47257.87,40970.47 ; U29.57@47257.87,41194.88 U29.13@47257.87,41238.19 ; U28.30@47257.87,42029.53 U28.57@47257.87,42072.83 ; U28.57@47257.87,42297.24 U28.13@47257.87,42340.55 ; U27.30@47257.87,43131.89 U27.57@47257.87,43175.2 ; U27.57@47257.87,43399.61 U27.13@47257.87,43442.91 ; U30.31@47277.56,39824.8 U30.57@47277.56,39868.11 ; U30.57@47277.56,40092.52 U30.12@47277.56,40135.83 ; U29.31@47277.56,40927.17 U29.57@47277.56,40970.47 ; U29.57@47277.56,41194.88 U29.12@47277.56,41238.19 ; U28.31@47277.56,42029.53 U28.57@47277.56,42072.83 ; U28.57@47277.56,42297.24 U28.12@47277.56,42340.55 ; U27.31@47277.56,43131.89 U27.57@47277.56,43175.2 ; U27.57@47277.56,43399.61 U27.12@47277.56,43442.91 ; U30.35@47356.3,39824.8 U30.57@47356.3,39868.11 ; U30.57@47356.3,40092.52 U30.8@47356.3,40135.83 ; U29.35@47356.3,40927.17 U29.57@47356.3,40970.47 ; U29.57@47356.3,41194.88 U29.8@47356.3,41238.19 ; U28.35@47356.3,42029.53 U28.57@47356.3,42072.83 ; U28.57@47356.3,42297.24 U28.8@47356.3,42340.55 ; U27.35@47356.3,43131.89 U27.57@47356.3,43175.2 ; U27.57@47356.3,43399.61 U27.8@47356.3,43442.91 ; U30.57@47454.72,40092.52 U30.3@47454.72,40135.83 ; U29.57@47454.72,41194.88 U29.3@47454.72,41238.19 ; U28.57@47454.72,42297.24 U28.3@47454.72,42340.55 ; U27.57@47454.72,43399.61 U27.3@47454.72,43442.91 ; U28.57@47472.44,42291.34 47494.09,42312.99 U28.56@47521.65,42312.99 ; U30.41@47474.41,39824.8 U30.57@47474.41,39868.11 ; U29.41@47474.41,40927.17 U29.57@47474.41,40970.47 ; U28.41@47474.41,42029.53 U28.57@47474.41,42072.83 ; U27.41@47474.41,43131.89 U27.57@47474.41,43175.2 ; U27.57@47476.38,43397.64 47494.09,43415.35 U27.56@47521.65,43415.35 ; U30.57@47478.35,39911.42 U30.46@47521.65,39911.42 ; U30.57@47478.35,39990.16 U30.50@47521.65,39990.16 ; U30.57@47478.35,40029.53 U30.52@47521.65,40029.53 ; U30.57@47478.35,40049.21 U30.53@47521.65,40049.21 ; U29.57@47478.35,41013.78 U29.46@47521.65,41013.78 ; U29.57@47478.35,41092.52 U29.50@47521.65,41092.52 ; U29.57@47478.35,41131.89 U29.52@47521.65,41131.89 ; U29.57@47478.35,41151.57 U29.53@47521.65,41151.57 ; U28.57@47478.35,42116.14 U28.46@47521.65,42116.14 ; U28.57@47478.35,42194.88 U28.50@47521.65,42194.88 ; U28.57@47478.35,42234.25 U28.52@47521.65,42234.25 ; U28.57@47478.35,42253.94 U28.53@47521.65,42253.94 ; U27.57@47478.35,43218.5 U27.46@47521.65,43218.5 ; U27.57@47478.35,43297.24 U27.50@47521.65,43297.24 ; U27.57@47478.35,43336.61 U27.52@47521.65,43336.61 ; U27.57@47478.35,43356.3 U27.53@47521.65,43356.3 ; U30.57@47480.32,40094.49 47494.09,40108.27 U30.56@47521.65,40108.27 ; U29.57@47480.32,41196.85 47494.09,41210.63 U29.56@47521.65,41210.63 ; U30.57@47484.25,39862.2 47494.09,39852.36 U30.42@47494.09,39824.8 ; U28.57@47484.25,42066.93 47494.09,42057.09 U28.42@47494.09,42029.53 ; U29.57@47488.19,40960.63 47494.09,40954.72 U29.42@47494.09,40927.17 ; U27.57@47488.19,43165.35 47494.09,43159.45 U27.42@47494.09,43131.89 ; U31.56@48438.98,39852.36 48466.54,39852.36 U31.57@48476.38,39862.2 ; U31.53@48438.98,39911.42 U31.57@48482.28,39911.42 ; U31.52@48438.98,39931.1 U31.57@48482.28,39931.1 ; U31.50@48438.98,39970.47 U31.57@48482.28,39970.47 ; U31.46@48438.98,40049.21 U31.57@48482.28,40049.21 ; U32.56@48438.98,40954.72 48466.54,40954.72 U32.57@48476.38,40964.57 ; U32.53@48438.98,41013.78 U32.57@48482.28,41013.78 ; U32.52@48438.98,41033.46 U32.57@48482.28,41033.46 ; U32.50@48438.98,41072.83 U32.57@48482.28,41072.83 ; U32.46@48438.98,41151.57 U32.57@48482.28,41151.57 ; U33.56@48438.98,42057.09 48466.54,42057.09 U33.57@48472.44,42062.99 ; U33.53@48438.98,42116.14 U33.57@48474.41,42116.14 ; U33.52@48438.98,42135.83 U33.57@48482.28,42135.83 ; U33.50@48438.98,42175.2 U33.57@48474.41,42175.2 ; U33.46@48438.98,42253.94 U33.57@48474.41,42253.94 ; U34.56@48438.98,43159.45 48470.47,43159.45 U34.57@48476.38,43165.35 ; U34.53@48438.98,43218.5 U34.57@48478.35,43218.5 ; U34.52@48438.98,43238.19 U34.57@48474.41,43238.19 ; U34.50@48438.98,43277.56 U34.57@48474.41,43277.56 ; U34.46@48438.98,43356.3 U34.57@48474.41,43356.3 ; U31.42@48466.54,40135.83 48466.54,40108.27 U31.57@48482.28,40092.52 ; U32.42@48466.54,41238.19 48466.54,41210.63 48484.25,41192.91 48486.22,41194.88 U32.41@48486.22,41238.19 ; U33.42@48466.54,42340.55 48466.54,42312.99 U33.57@48472.44,42307.09 ; U34.42@48466.54,43442.91 48466.54,43415.35 U34.57@48486.22,43395.67 ; U31.57@48486.22,40092.52 U31.41@48486.22,40135.83 ; U33.57@48486.22,42305.12 U33.41@48486.22,42340.55 ; U34.41@48486.22,43442.91 U34.57@48486.22,43395.67 ; U31.3@48505.91,39824.8 U31.57@48505.91,39868.11 ; U32.3@48505.91,40927.17 U32.57@48505.91,40970.47 ; U33.3@48505.91,42029.53 U33.57@48505.91,42064.96 ; U34.3@48505.91,43131.89 U34.57@48505.91,43198.82 ; v2(48594.49,43287.4) v2(48547.24,43334.65) 48505.91,43375.98 v2(48500,43381.89) U34.57@48486.22,43395.67 ; U31.8@48604.33,39824.8 U31.57@48604.33,39868.11 ; U31.57@48604.33,40092.52 U31.35@48604.33,40135.83 ; U32.8@48604.33,40927.17 U32.57@48604.33,40970.47 ; U32.57@48604.33,41194.88 U32.35@48604.33,41238.19 ; U33.8@48604.33,42029.53 U33.57@48604.33,42064.96 ; U33.57@48604.33,42305.12 U33.35@48604.33,42340.55 ; U34.8@48604.33,43131.89 U34.57@48604.33,43277.56 ; U34.35@48604.33,43442.91 48604.33,43297.24 U34.22@48750,43297.24 ; U34.57@48643.7,43238.19 U34.19@48750,43238.19 ; U34.57@48663.39,43218.5 U34.18@48750,43218.5 ; U31.12@48683.07,39824.8 U31.57@48683.07,39868.11 ; U31.57@48683.07,40092.52 U31.31@48683.07,40135.83 ; U32.12@48683.07,40927.17 U32.57@48683.07,40970.47 ; U32.57@48683.07,41194.88 U32.31@48683.07,41238.19 ; U33.12@48683.07,42029.53 U33.57@48683.07,42064.96 ; U33.57@48683.07,42305.12 U33.31@48683.07,42340.55 ; U34.12@48683.07,43131.89 U34.57@48683.07,43198.82 ; U34.31@48683.07,43442.91 48683.07,43375.98 U34.26@48750,43375.98 ; U31.13@48702.76,39824.8 U31.57@48702.76,39868.11 ; U31.57@48702.76,40092.52 U31.30@48702.76,40135.83 ; U32.13@48702.76,40927.17 U32.57@48702.76,40970.47 ; U32.57@48702.76,41194.88 U32.30@48702.76,41238.19 ; U33.13@48702.76,42029.53 U33.57@48702.76,42064.96 ; U33.57@48702.76,42305.12 U33.30@48702.76,42340.55 ; U34.13@48702.76,43131.89 U34.57@48702.76,43179.13 ; U34.57@48702.76,43395.67 U34.30@48702.76,43442.91 ; U31.57@48706.69,39872.05 U31.16@48750,39872.05 ; U31.57@48706.69,39911.42 U31.18@48750,39911.42 ; U31.57@48706.69,39931.1 U31.19@48750,39931.1 ; U31.57@48706.69,39950.79 U31.20@48750,39950.79 ; U31.57@48706.69,39990.16 U31.22@48750,39990.16 ; U31.57@48706.69,40009.84 U31.23@48750,40009.84 ; U31.57@48706.69,40068.9 U31.26@48750,40068.9 ; U32.57@48706.69,40974.41 U32.16@48750,40974.41 ; U32.57@48706.69,41013.78 U32.18@48750,41013.78 ; U32.57@48706.69,41033.46 U32.19@48750,41033.46 ; U32.57@48706.69,41092.52 U32.22@48750,41092.52 ; U32.57@48706.69,41112.2 U32.23@48750,41112.2 ; U32.57@48706.69,41171.26 U32.26@48750,41171.26 ; U32.57@48712.6,40964.57 48722.44,40954.72 U32.15@48750,40954.72 ; U33.57@48714.57,42076.77 U33.16@48750,42076.77 ; U33.57@48714.57,42116.14 U33.18@48750,42116.14 ; U33.57@48714.57,42135.83 U33.19@48750,42135.83 ; U33.57@48714.57,42155.51 U33.20@48750,42155.51 ; U33.57@48714.57,42194.88 U33.22@48750,42194.88 ; U33.57@48714.57,42273.62 U33.26@48750,42273.62 ; U31.57@48716.54,39858.27 48722.44,39852.36 U31.15@48750,39852.36 ; U33.57@48716.54,42062.99 48722.44,42057.09 U33.15@48750,42057.09 ; U34.15@48750,43159.45 48722.44,43159.45 U34.57@48702.76,43179.13 ; U34.16@48750,43179.13 U34.57@48702.76,43179.13 ; U3.57@39875.98,43179.13 v2(39889.76,43192.91) U3.57@39895.67,43198.82 ; U3.57@39875.98,43395.67 v2(39889.76,43381.89) U3.57@39895.67,43375.98 ; U3.57@39895.67,43198.82 U3.57@39935.04,43238.19 ; U3.57@39895.67,43375.98 U3.57@39915.35,43356.3 ; U3.57@39915.35,43356.3 U3.57@39935.04,43336.61 ; U3.57@39935.04,43238.19 v2(39937.01,43240.16) U3.57@39974.41,43277.56 ; U3.57@39935.04,43336.61 v2(39937.01,43334.65) U3.57@39954.72,43316.93 ; U3.57@39954.72,43316.93 U3.57@39974.41,43297.24 ; U3.57@39974.41,43297.24 v2(39984.25,43287.4) ; v2(39984.25,43287.4) v2(40031.5,43240.16) U3.57@40053.15,43218.5 ; v2(39984.25,43287.4) U3.57@39994.09,43297.24 ; U3.57@39994.09,43297.24 v2(40031.5,43334.65) U3.57@40033.46,43336.61 ; U3.57@40033.46,43336.61 U3.57@40053.15,43356.3 ; U3.57@40053.15,43218.5 40072.83,43198.82 v2(40078.74,43192.91) U3.57@40092.52,43179.13 ; U3.57@40053.15,43356.3 U3.57@40072.83,43375.98 ; U10.57@41124.02,43198.82 U10.57@41143.7,43218.5 ; U10.57@41143.7,43218.5 U10.57@41163.39,43238.19 ; U10.57@41261.81,43238.19 U10.57@41281.5,43218.5 ; U10.57@41281.5,43218.5 U10.57@41301.18,43198.82 ; U10.57@41301.18,43198.82 v2(41307.09,43192.91) U10.57@41320.87,43179.13 ; U17.57@43545.28,42312.99 U17.42@43545.28,42340.55 43545.28,42312.99 ; 43801.18,42312.99 U17.28@43828.74,42312.99 43801.18,42312.99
